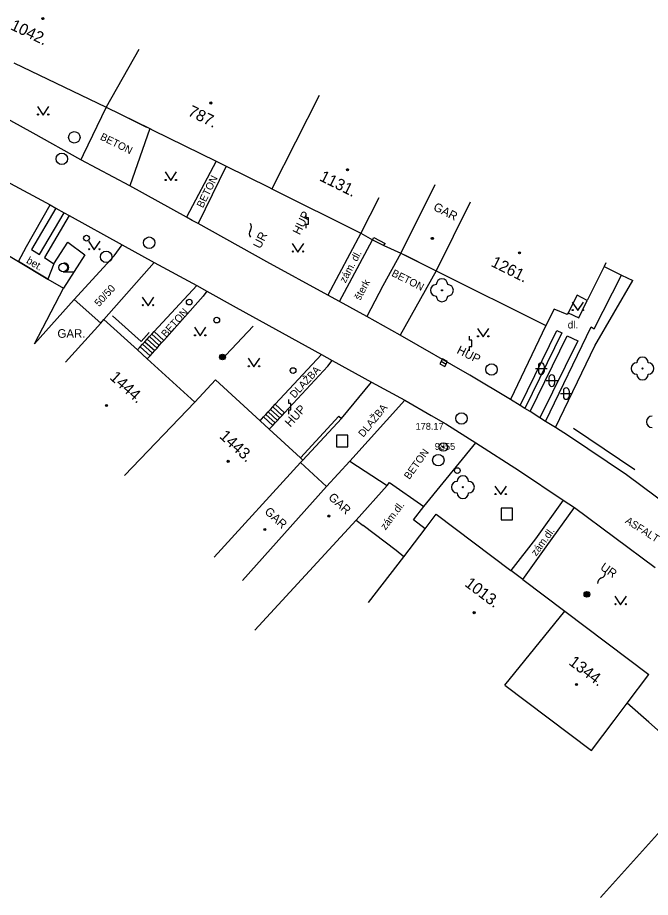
# Model space of a CAD drawing. Extents: x -539244 to -537359, y -1183785 to -1181851.
# Drawn here: x -538435.4 to -538380.2, y -1183538.2 to -1183461.4 of the extents above; entities that cross this region are included whole.
import ezdxf

# ---------------------------------------------------------------- set-up
doc = ezdxf.new("R2010")
doc.units = 0
for name, color, linetype in [('Vrstva 10', 7, 'Continuous'), ('Vrstva 11', 7, 'Continuous'), ('Vrstva 21', 7, 'Continuous'), ('Vrstva 22', 7, 'Continuous'), ('Vrstva 23', 7, 'Continuous'), ('Vrstva 24', 7, 'Continuous'), ('Vrstva 25', 7, 'Continuous'), ('Vrstva 26', 7, 'Continuous'), ('Vrstva 27', 7, 'Continuous'), ('Vrstva 28', 7, 'Continuous'), ('Vrstva 36', 7, 'Continuous'), ('Vrstva 39', 7, 'Continuous'), ('Vrstva 40', 7, 'Continuous'), ('Vrstva 41', 7, 'Continuous'), ('Vrstva 47', 7, 'Continuous'), ('Vrstva 5', 7, 'Continuous'), ('Vrstva 6', 7, 'Continuous'), ('Vrstva 7', 7, 'Continuous'), ('Vrstva 8', 7, 'Continuous')]:
    doc.layers.add(name, color=color, linetype=linetype)

msp = doc.modelspace()

# ---------------------------------------------------------------- linework, layer by layer
at = {"layer": 'Vrstva 10'}
for p, q in [((-538425.64, -1183476.11), (-538429.9, -1183473.84)), ((-538420.7, -1183478.85), (-538425.64, -1183476.11)), ((-538430.92, -1183478.71), (-538426.31, -1183481.25)), ((-538413.68, -1183482.75), (-538419.68, -1183479.41)), ((-538408.35, -1183485.66), (-538413.68, -1183482.75)), ((-538418.92, -1183485.31), (-538416.37, -1183486.73)), ((-538407.33, -1183486.2), (-538408.35, -1183485.66)), ((-538404.95, -1183487.52), (-538407.33, -1183486.2)), ((-538416.37, -1183486.73), (-538408.9, -1183490.82)), ((-538402.04, -1183489.14), (-538404.95, -1183487.52)), ((-538395.96, -1183492.62), (-538402.04, -1183489.14)), ((-538392.43, -1183494.75), (-538395.96, -1183492.62)), ((-538387.36, -1183497.94), (-538388.5, -1183497.2)), ((-538382.31, -1183501.34), (-538387.36, -1183497.94)), ((-538375.8, -1183506.19), (-538382.31, -1183501.34)), ((-538387.81, -1183503.53), (-538386.84, -1183504.18)), ((-538386.84, -1183504.18), (-538379.8, -1183509.42))]:
    msp.add_line(p, q, dxfattribs=at)
for points in [[(-538429.9, -1183473.84), (-538434.07, -1183471.51), (-538437.73, -1183469.5)], [(-538437.31, -1183475.17), (-538436.44, -1183475.69), (-538432.58, -1183477.78), (-538432.1, -1183478.06), (-538431.36, -1183478.47), (-538430.92, -1183478.71)], [(-538419.68, -1183479.41), (-538420.2, -1183479.13), (-538420.7, -1183478.85)], [(-538426.31, -1183481.25), (-538423.5, -1183482.79), (-538419.8, -1183484.8), (-538418.92, -1183485.31)], [(-538408.9, -1183490.82), (-538407.97, -1183491.35), (-538404.56, -1183493.24), (-538401.65, -1183494.83)], [(-538401.65, -1183494.83), (-538399.33, -1183496.15), (-538398.07, -1183496.87), (-538395.44, -1183498.55)], [(-538388.5, -1183497.2), (-538389.36, -1183496.67), (-538389.85, -1183496.36), (-538390.69, -1183495.8), (-538391.16, -1183495.54), (-538391.57, -1183495.28), (-538392.43, -1183494.75)], [(-538395.44, -1183498.55), (-538391.63, -1183500.97), (-538387.81, -1183503.53)]]:
    msp.add_lwpolyline(points, dxfattribs=at)
at = {"layer": 'Vrstva 11'}
for p, q in [((-538423.899, -1183471.117), (-538425.64, -1183476.11)), ((-538418.108, -1183473.968), (-538420.7, -1183478.85)), ((-538417.24, -1183474.395), (-538419.68, -1183479.41)), ((-538405.47, -1183480.25), (-538408.35, -1183485.66)), ((-538407.33, -1183486.2), (-538404.45, -1183480.81)), ((-538401.98, -1183481.98), (-538403.55, -1183484.84)), ((-538432.26, -1183482.93), (-538432.79, -1183484.25)), ((-538427.9, -1183487.79), (-538423.5, -1183482.79)), ((-538398.91, -1183483.53), (-538402.04, -1183489.14)), ((-538385.11, -1183488.58), (-538382.72, -1183483.91)), ((-538423.517, -1183488.823), (-538419.8, -1183484.8)), ((-538418.92, -1183485.31), (-538419.24, -1183485.75)), ((-538403.55, -1183484.84), (-538404.95, -1183487.52)), ((-538422.66, -1183489.6), (-538419.24, -1183485.75)), ((-538389.33, -1183488.31), (-538392.43, -1183494.75)), ((-538389.36, -1183496.67), (-538385.37, -1183488.42)), ((-538385.37, -1183488.42), (-538385.11, -1183488.58)), ((-538423.92, -1183489.267), (-538423.063, -1183490.044)), ((-538423.718, -1183489.045), (-538422.861, -1183489.822)), ((-538423.517, -1183488.823), (-538422.66, -1183489.6)), ((-538391.57, -1183495.28), (-538388.37, -1183488.74)), ((-538387.95, -1183488.94), (-538391.16, -1183495.54)), ((-538390.69, -1183495.8), (-538387.46, -1183489.19)), ((-538388.37, -1183488.74), (-538387.95, -1183488.94)), ((-538387.46, -1183489.19), (-538386.54, -1183489.63)), ((-538424.524, -1183489.934), (-538423.667, -1183490.711)), ((-538424.323, -1183489.712), (-538423.466, -1183490.489)), ((-538424.121, -1183489.489), (-538423.264, -1183490.266)), ((-538386.54, -1183489.63), (-538389.85, -1183496.36)), ((-538424.726, -1183490.156), (-538423.868, -1183490.934)), ((-538412.957, -1183495.179), (-538408.9, -1183490.82)), ((-538408.35, -1183491.85), (-538407.97, -1183491.35)), ((-538412.15, -1183495.92), (-538408.35, -1183491.85)), ((-538407.18, -1183496.42), (-538404.56, -1183493.24)), ((-538413.159, -1183495.399), (-538412.352, -1183496.14)), ((-538412.957, -1183495.179), (-538412.15, -1183495.92)), ((-538406.44, -1183500.15), (-538401.65, -1183494.83)), ((-538413.768, -1183496.062), (-538412.961, -1183496.803)), ((-538413.565, -1183495.841), (-538412.758, -1183496.582)), ((-538413.362, -1183495.62), (-538412.555, -1183496.361)), ((-538413.971, -1183496.283), (-538413.164, -1183497.024)), ((-538399.97, -1183504.1), (-538395.44, -1183498.55))]:
    msp.add_line(p, q, dxfattribs=at)
for points in [[(-538427.69, -1183469.25), (-538429.7, -1183473.4), (-538429.9, -1183473.84)], [(-538435.34, -1183482.72), (-538434.65, -1183481.4), (-538432.58, -1183477.78)], [(-538432.1, -1183478.06), (-538434.23, -1183481.66), (-538433.51, -1183482.11), (-538431.36, -1183478.47)], [(-538430.92, -1183478.71), (-538433.07, -1183482.38), (-538432.26, -1183482.93)], [(-538430.494, -1183486.02), (-538427.01, -1183482.21), (-538426.31, -1183481.25)], [(-538387.39, -1183487.2), (-538386.45, -1183487.63), (-538385.72, -1183486.11)], [(-538424.979, -1183490.436), (-538424.726, -1183490.156), (-538424.524, -1183489.934), (-538424.323, -1183489.712), (-538424.121, -1183489.489), (-538423.92, -1183489.267), (-538423.718, -1183489.045), (-538423.517, -1183488.823)], [(-538424.121, -1183491.213), (-538423.868, -1183490.934), (-538423.667, -1183490.711), (-538423.466, -1183490.489), (-538423.264, -1183490.266), (-538423.063, -1183490.044), (-538422.861, -1183489.822), (-538422.66, -1183489.6)], [(-538414.273, -1183496.611), (-538413.971, -1183496.283), (-538413.768, -1183496.062), (-538413.565, -1183495.841), (-538413.362, -1183495.62), (-538413.159, -1183495.399), (-538412.957, -1183495.179)], [(-538413.466, -1183497.352), (-538413.164, -1183497.024), (-538412.961, -1183496.803), (-538412.758, -1183496.582), (-538412.555, -1183496.361), (-538412.352, -1183496.14), (-538412.15, -1183495.92)], [(-538403.17, -1183502.25), (-538402.99, -1183502.01), (-538399.97, -1183504.1)], [(-538387.81, -1183503.53), (-538390.25, -1183506.91), (-538392.39, -1183509.69)], [(-538399.876, -1183506.034), (-538400.891, -1183505.265), (-538399.97, -1183504.1)], [(-538391.35, -1183510.46), (-538389.32, -1183507.63), (-538386.84, -1183504.18)]]:
    msp.add_lwpolyline(points, dxfattribs=at)
at = {"layer": 'Vrstva 21'}
for radius in [0.375, 0.05]:
    msp.add_circle((-538398.28, -1183498.9), radius, dxfattribs=at)
at = {"layer": 'Vrstva 22'}
for centre in [(-538398.4, -1183485.23), (-538380.9, -1183492.05), (-538396.57, -1183502.41)]:
    msp.add_circle(centre, 0.05, dxfattribs=at)
for centre, start, end in [((-538398.4, -1183484.73), 0, 180), ((-538398.9, -1183485.23), 90, 270), ((-538397.9, -1183485.23), 270, 90), ((-538398.4, -1183485.73), 180, 0), ((-538381.4, -1183492.05), 90, 270), ((-538380.9, -1183491.55), 0, 180), ((-538380.4, -1183492.05), 270, 90), ((-538380.9, -1183492.55), 180, 0), ((-538380.06, -1183496.71), 90, 270), ((-538396.57, -1183501.91), 0, 180), ((-538397.07, -1183502.41), 90, 270), ((-538396.07, -1183502.41), 270, 90), ((-538396.57, -1183502.91), 180, 0)]:
    msp.add_arc(centre, 0.5, start, end, dxfattribs=at)
at = {"layer": 'Vrstva 23'}
msp.add_line((-538388.5, -1183497.2), (-538385.05, -1183490.07), dxfattribs=at)
msp.add_lwpolyline([(-538432.26, -1183482.93), (-538431.04, -1183481.03), (-538429.55, -1183482.12), (-538431.44, -1183485.05)], dxfattribs=at)
at = {"layer": 'Vrstva 24'}
for p, q in [((-538410.239, -1183478.899), (-538410.24, -1183478.531)), ((-538410.056, -1183478.9), (-538410.239, -1183478.899)), ((-538410.056, -1183479.452), (-538410.056, -1183478.9)), ((-538410.24, -1183479.82), (-538410.239, -1183479.452)), ((-538410.239, -1183479.452), (-538410.056, -1183479.452)), ((-538395.989, -1183489.589), (-538395.99, -1183489.221)), ((-538395.806, -1183489.59), (-538395.989, -1183489.589)), ((-538395.806, -1183490.142), (-538395.806, -1183489.59)), ((-538395.99, -1183490.51), (-538395.989, -1183490.142)), ((-538395.989, -1183490.142), (-538395.806, -1183490.142)), ((-538411.769, -1183495.119), (-538411.77, -1183494.751)), ((-538411.586, -1183495.12), (-538411.769, -1183495.119)), ((-538411.586, -1183495.672), (-538411.586, -1183495.12)), ((-538411.77, -1183496.04), (-538411.769, -1183495.672)), ((-538411.769, -1183495.672), (-538411.586, -1183495.672))]:
    msp.add_line(p, q, dxfattribs=at)
for centre, start, end in [((-538414.72, -1183480.29), 143.1301, 216.8699), ((-538415.52, -1183479.69), 323.1301, 36.8699), ((-538384.64, -1183509.857), 288.20446, 1.94426), ((-538384.327, -1183510.807), 108.20446, 181.94426)]:
    msp.add_arc(centre, 0.5, start, end, dxfattribs=at)
at = {"layer": 'Vrstva 25'}
for centre, radius in [((-538417.55, -1183491.05), 0.25), ((-538417.55, -1183491.05), 0.2), ((-538417.55, -1183491.05), 0.15), ((-538417.55, -1183491.05), 0.1), ((-538417.55, -1183491.05), 0.05), ((-538385.75, -1183511.76), 0.25), ((-538385.75, -1183511.76), 0.2), ((-538385.75, -1183511.76), 0.15), ((-538385.75, -1183511.76), 0.1), ((-538385.75, -1183511.76), 0.05)]:
    msp.add_circle(centre, radius, dxfattribs=at)
at = {"layer": 'Vrstva 26'}
for points in [[(-538407.6, -1183498.88), (-538406.6, -1183498.88), (-538406.6, -1183497.88), (-538407.6, -1183497.88)], [(-538393.23, -1183505.25), (-538392.23, -1183505.25), (-538392.23, -1183504.25), (-538393.23, -1183504.25)]]:
    msp.add_lwpolyline(points, close=True, dxfattribs=at)
at = {"layer": 'Vrstva 27'}
msp.add_line((-538398.466, -1183491.415), (-538398.034, -1183491.665), dxfattribs=at)
msp.add_lwpolyline([(-538398.592, -1183491.631), (-538398.159, -1183491.882), (-538397.908, -1183491.449), (-538398.341, -1183491.198)], close=True, dxfattribs=at)
for centre in [(-538430.481, -1183471.882), (-538431.572, -1183473.75), (-538423.944, -1183481.076), (-538427.698, -1183482.308), (-538394.068, -1183492.135), (-538396.7, -1183496.41), (-538398.72, -1183500.05)]:
    msp.add_circle(centre, 0.5, dxfattribs=at)
at = {"layer": 'Vrstva 28'}
for centre in [(-538429.42, -1183480.68), (-538420.45, -1183486.26), (-538418.05, -1183487.83), (-538411.39, -1183492.23), (-538397.06, -1183500.96)]:
    msp.add_circle(centre, 0.25, dxfattribs=at)
at = {"layer": 'Vrstva 36'}
for p, q in [((-538431.462, -1183483.61), (-538430.462, -1183483.61)), ((-538390.233, -1183492.056), (-538389.233, -1183492.056)), ((-538389.983, -1183491.806), (-538389.983, -1183492.306)), ((-538389.483, -1183491.806), (-538389.483, -1183492.306)), ((-538389.317, -1183493.112), (-538388.317, -1183493.112)), ((-538389.067, -1183492.862), (-538389.067, -1183493.362)), ((-538388.567, -1183492.862), (-538388.567, -1183493.362)), ((-538388.049, -1183494.242), (-538387.049, -1183494.242)), ((-538387.799, -1183493.992), (-538387.799, -1183494.492)), ((-538387.299, -1183493.992), (-538387.299, -1183494.492))]:
    msp.add_line(p, q, dxfattribs=at)
for points in [[(-538433.702, -1183469.184), (-538433.202, -1183469.934), (-538432.702, -1183469.184)], [(-538422.561, -1183474.896), (-538422.061, -1183475.646), (-538421.561, -1183474.896)], [(-538429.237, -1183480.946), (-538428.737, -1183481.696), (-538428.237, -1183480.946)], [(-538411.465, -1183481.137), (-538410.965, -1183481.887), (-538410.465, -1183481.137)], [(-538424.547, -1183485.821), (-538424.047, -1183486.571), (-538423.547, -1183485.821)], [(-538387.043, -1183486.255), (-538386.543, -1183487.005), (-538386.043, -1183486.255)], [(-538420.003, -1183488.459), (-538419.503, -1183489.209), (-538419.003, -1183488.459)], [(-538395.308, -1183488.55), (-538394.808, -1183489.3), (-538394.308, -1183488.55)], [(-538415.305, -1183491.158), (-538414.805, -1183491.908), (-538414.305, -1183491.158)], [(-538393.775, -1183502.308), (-538393.275, -1183503.058), (-538392.775, -1183502.308)], [(-538383.31, -1183511.92), (-538382.81, -1183512.67), (-538382.31, -1183511.92)]]:
    msp.add_lwpolyline(points, dxfattribs=at)
for centre, radius in [((-538433.652, -1183469.884), 0.05), ((-538432.753, -1183469.884), 0.05), ((-538422.511, -1183475.596), 0.05), ((-538421.612, -1183475.596), 0.05), ((-538429.187, -1183481.646), 0.05), ((-538428.288, -1183481.646), 0.05), ((-538411.415, -1183481.837), 0.05), ((-538410.516, -1183481.837), 0.05), ((-538431.462, -1183483.235), 0.375), ((-538424.497, -1183486.521), 0.05), ((-538423.598, -1183486.521), 0.05), ((-538386.993, -1183486.955), 0.05), ((-538386.094, -1183486.955), 0.05), ((-538419.953, -1183489.159), 0.05), ((-538419.054, -1183489.159), 0.05), ((-538395.258, -1183489.25), 0.05), ((-538394.359, -1183489.25), 0.05), ((-538415.255, -1183491.858), 0.05), ((-538414.356, -1183491.858), 0.05), ((-538393.725, -1183503.008), 0.05), ((-538392.826, -1183503.008), 0.05), ((-538383.26, -1183512.62), 0.05), ((-538382.361, -1183512.62), 0.05)]:
    msp.add_circle(centre, radius, dxfattribs=at)
for centre, radius, start, end in [((-538431.337, -1183483.235), 0.375, 260.40593, 99.59406), ((-538389.733, -1183491.806), 0.25, 0, 180), ((-538389.733, -1183492.306), 0.25, 180, 0), ((-538388.817, -1183492.862), 0.25, 0, 180), ((-538388.817, -1183493.362), 0.25, 180, 0), ((-538387.549, -1183493.992), 0.25, 0, 180), ((-538387.549, -1183494.492), 0.25, 180, 0)]:
    msp.add_arc(centre, radius, start, end, dxfattribs=at)
at = {"layer": 'Vrstva 39'}
for centre, radius in [((-538433.237, -1183461.519), 0.09), ((-538433.237, -1183461.519), 0.0398), ((-538418.569, -1183468.883), 0.09), ((-538418.569, -1183468.883), 0.0398), ((-538406.649, -1183474.704), 0.09), ((-538406.649, -1183474.704), 0.0398), ((-538399.239, -1183480.696), 0.09), ((-538399.239, -1183480.696), 0.0398), ((-538391.626, -1183481.966), 0.09), ((-538391.626, -1183481.966), 0.0398), ((-538427.667, -1183495.28), 0.09), ((-538427.667, -1183495.28), 0.0398), ((-538417.059, -1183500.155), 0.09), ((-538417.059, -1183500.155), 0.0398), ((-538408.279, -1183504.929), 0.09), ((-538408.279, -1183504.929), 0.0398), ((-538413.862, -1183506.097), 0.09), ((-538413.862, -1183506.097), 0.0398), ((-538395.591, -1183513.359), 0.09), ((-538395.591, -1183513.359), 0.0398), ((-538386.665, -1183519.633), 0.09), ((-538386.665, -1183519.633), 0.0398)]:
    msp.add_circle(centre, radius, dxfattribs=at)
at = {"layer": 'Vrstva 5'}
for p, q in [((-538424.85, -1183464.21), (-538427.69, -1183469.25)), ((-538435.749, -1183465.383), (-538427.69, -1183469.25)), ((-538409.11, -1183468.23), (-538413.25, -1183476.36)), ((-538427.69, -1183469.25), (-538423.899, -1183471.117)), ((-538423.899, -1183471.117), (-538423.629, -1183471.25)), ((-538423.629, -1183471.25), (-538418.108, -1183473.968)), ((-538417.24, -1183474.395), (-538413.519, -1183476.227)), ((-538413.519, -1183476.227), (-538413.25, -1183476.36)), ((-538399.03, -1183476.02), (-538401.98, -1183481.98)), ((-538413.25, -1183476.36), (-538405.47, -1183480.25)), ((-538403.92, -1183477.16), (-538405.47, -1183480.25)), ((-538395.95, -1183477.53), (-538398.91, -1183483.53)), ((-538401.98, -1183481.98), (-538398.91, -1183483.53)), ((-538398.91, -1183483.53), (-538389.33, -1183488.31)), ((-538433.97, -1183489.91), (-538431.44, -1183485.05)), ((-538433.97, -1183489.91), (-538430.494, -1183486.02)), ((-538430.494, -1183486.02), (-538428.168, -1183488.086)), ((-538386.61, -1183485.64), (-538387.39, -1183487.2)), ((-538385.72, -1183486.11), (-538386.61, -1183485.64)), ((-538388.619, -1183486.884), (-538389.33, -1183488.31)), ((-538387.46, -1183487.33), (-538388.619, -1183486.884)), ((-538387.39, -1183487.2), (-538387.46, -1183487.33)), ((-538431.257, -1183491.496), (-538428.168, -1183488.086)), ((-538428.168, -1183488.086), (-538427.9, -1183487.79)), ((-538424.979, -1183490.436), (-538427.9, -1183487.79)), ((-538424.121, -1183491.213), (-538424.979, -1183490.436)), ((-538419.962, -1183494.981), (-538424.121, -1183491.213)), ((-538419.962, -1183494.981), (-538418.17, -1183493.03)), ((-538418.17, -1183493.03), (-538414.273, -1183496.611)), ((-538426.11, -1183501.39), (-538419.962, -1183494.981)), ((-538414.273, -1183496.611), (-538413.466, -1183497.352)), ((-538413.466, -1183497.352), (-538410.75, -1183499.847)), ((-538410.75, -1183499.847), (-538410.53, -1183500.05)), ((-538418.28, -1183508.53), (-538410.732, -1183500.27)), ((-538410.732, -1183500.27), (-538410.53, -1183500.05)), ((-538408.464, -1183502.353), (-538410.732, -1183500.27)), ((-538408.464, -1183502.353), (-538406.44, -1183500.15)), ((-538406.44, -1183500.15), (-538403.17, -1183502.25)), ((-538403.17, -1183502.25), (-538405.9, -1183505.29)), ((-538415.8, -1183510.55), (-538408.464, -1183502.353)), ((-538405.9, -1183505.29), (-538414.72, -1183514.89)), ((-538398.91, -1183504.76), (-538392.39, -1183509.69)), ((-538404.81, -1183512.48), (-538401.73, -1183508.48)), ((-538391.35, -1183510.46), (-538387.69, -1183513.23)), ((-538392.91, -1183519.69), (-538387.69, -1183513.23)), ((-538387.69, -1183513.23), (-538380.36, -1183518.77)), ((-538392.91, -1183519.69), (-538385.351, -1183525.377)), ((-538385.351, -1183525.377), (-538383.375, -1183522.759))]:
    msp.add_line(p, q, dxfattribs=at)
for points in [[(-538439.174, -1183480.442), (-538435.34, -1183482.72), (-538432.79, -1183484.25), (-538431.44, -1183485.05)], [(-538384.1, -1183482.83), (-538384.25, -1183483.14), (-538385.72, -1183486.11)], [(-538401.73, -1183508.48), (-538399.876, -1183506.034), (-538398.91, -1183504.76)], [(-538383.375, -1183522.759), (-538382.24, -1183521.25), (-538380.36, -1183518.77)], [(-538384.57, -1183538.21), (-538376.18, -1183528.92), (-538375.03, -1183527.64)]]:
    msp.add_lwpolyline(points, dxfattribs=at)
at = {"layer": 'Vrstva 6'}
for p, q in [((-538426.58, -1183469.8), (-538424.18, -1183470.98)), ((-538418.108, -1183473.968), (-538417.24, -1183474.395)), ((-538401.67, -1183482.14), (-538399.32, -1183483.32)), ((-538432.79, -1183484.25), (-538435.34, -1183482.72)), ((-538428.168, -1183488.086), (-538430.27, -1183486.22)), ((-538391.35, -1183510.46), (-538392.39, -1183509.69))]:
    msp.add_line(p, q, dxfattribs=at)
at = {"layer": 'Vrstva 7'}
for p, q in [((-538404.45, -1183480.81), (-538404.357, -1183480.633)), ((-538404.45, -1183480.81), (-538403.46, -1183481.33)), ((-538404.357, -1183480.633), (-538403.367, -1183481.153)), ((-538403.46, -1183481.33), (-538403.367, -1183481.153)), ((-538385.05, -1183490.07), (-538381.74, -1183484.38)), ((-538414.87, -1183488.37), (-538417.25, -1183490.9)), ((-538410.75, -1183499.847), (-538407.4, -1183496.217)), ((-538410.53, -1183500.05), (-538407.18, -1183496.42)), ((-538407.4, -1183496.217), (-538407.18, -1183496.42)), ((-538386.93, -1183497.25), (-538381.56, -1183500.87)), ((-538405.9, -1183505.29), (-538405.29, -1183505.75)), ((-538401.73, -1183508.48), (-538402.4, -1183507.93))]:
    msp.add_line(p, q, dxfattribs=at)
msp.add_lwpolyline([(-538427.14, -1183487.45), (-538424.656, -1183489.7), (-538423.94, -1183488.91)], dxfattribs=at)
at = {"layer": 'Vrstva 8'}
for p, q in [((-538405.47, -1183480.25), (-538404.45, -1183480.81)), ((-538403.46, -1183481.33), (-538401.98, -1183481.98)), ((-538402.4, -1183507.93), (-538405.29, -1183505.75))]:
    msp.add_line(p, q, dxfattribs=at)
for points in [[(-538384.25, -1183483.14), (-538382.72, -1183483.91), (-538381.74, -1183484.38)], [(-538377.049, -1183525.838), (-538380.34, -1183522.92), (-538382.24, -1183521.25)]]:
    msp.add_lwpolyline(points, dxfattribs=at)

# ---------------------------------------------------------------- texts
at = {"layer": 'Vrstva 22'}
msp.add_text('178.17', height=0.6, dxfattribs=at).set_placement((-538400.705, -1183497.4))
at = {"layer": 'Vrstva 23'}
msp.add_text('9855', height=0.6, dxfattribs=at).set_placement((-538399.03, -1183499.15))
at = {"layer": 'Vrstva 40'}
for s, rotation, p in [('BETON', 333.78518, (-538428.289, -1183472.042)), ('BETON', 63.78121, (-538419.263, -1183478.09)), ('bet.', 329.50315, (-538434.728, -1183482.808)), ('zám. dl.', 61.8346, (-538406.818, -1183484.638)), ('BETON', 333.21143, (-538402.85, -1183483.947)), ('šterk', 61.71389, (-538405.536, -1183486.152)), ('50/50', 47.55967, (-538428.321, -1183486.708)), ('BETON', 48.38494, (-538422.476, -1183489.392)), ('DLAŽBA', 46.9649, (-538411.268, -1183494.689)), ('DLAŽBA', 50.64565, (-538405.264, -1183498.098)), ('BETON', 54.50635, (-538401.241, -1183501.791)), ('zám.dl.', 52.96895, (-538403.323, -1183506.196)), ('ASFALT', 327.44335, (-538382.469, -1183505.492)), ('zám.dl.', 53.84562, (-538390.175, -1183508.475))]:
    msp.add_text(s, height=0.65, rotation=rotation, dxfattribs=at).set_placement(p)
msp.add_text('dl.', height=0.65, dxfattribs=at).set_placement((-538387.425, -1183488.561))
at = {"layer": 'Vrstva 41'}
for s, rotation, p in [('GAR', 333.21143, (-538399.217, -1183478.195)), ('HUP', 63.43495, (-538410.811, -1183480.458)), ('UR', 63.63994, (-538414.248, -1183481.656)), ('HUP', 333.53734, (-538397.166, -1183490.685)), ('HUP', 47.67714, (-538411.638, -1183497.21)), ('GAR', 317.43469, (-538408.37, -1183503.377)), ('GAR', 317.43469, (-538413.941, -1183504.622)), ('UR', 325.00798, (-538384.646, -1183509.546))]:
    msp.add_text(s, height=0.75, rotation=rotation, dxfattribs=at).set_placement(p)
msp.add_text('GAR.', height=0.75, dxfattribs=at).set_placement((-538431.955, -1183489.372))
at = {"layer": 'Vrstva 47'}
for s, rotation, p in [('1042.', 334.36826, (-538436.126, -1183462.429)), ('787.', 333.78518, (-538420.644, -1183469.934)), ('1131.', 333.43495, (-538409.158, -1183475.611)), ('1261.', 333.48281, (-538394.198, -1183483.087)), ('1444.', 317.82671, (-538427.459, -1183492.912)), ('1443.', 317.42171, (-538417.889, -1183498.042)), ('1013.', 322.95077, (-538396.487, -1183510.975)), ('1344.', 322.91808, (-538387.404, -1183517.833))]:
    msp.add_text(s, height=1, rotation=rotation, dxfattribs=at).set_placement(p)

doc.saveas('drawing.dxf')
